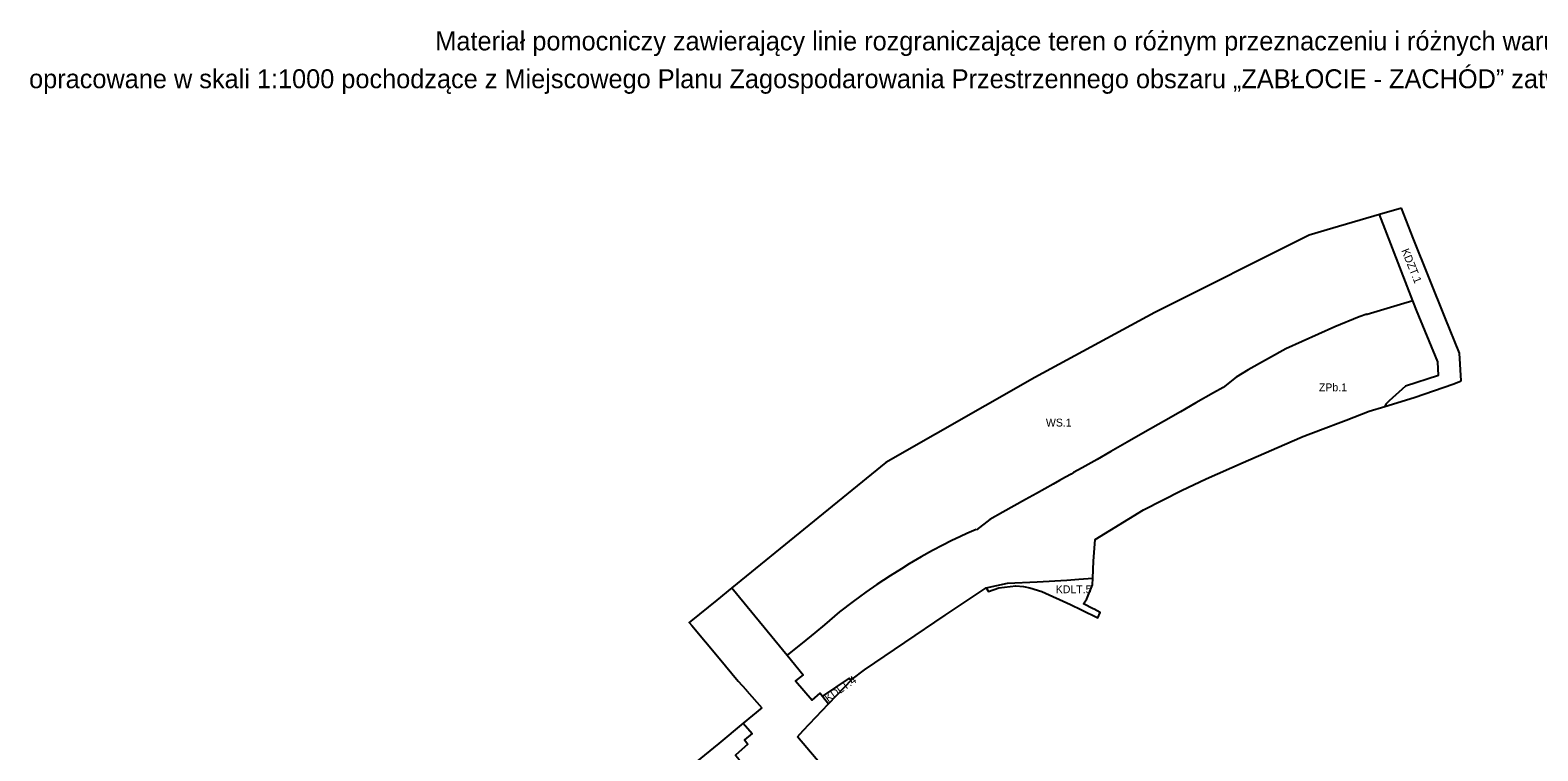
# Model space of a CAD drawing. Extents: x 7424719 to 7426158, y 5545504 to 5546892.
# Drawn here: x 7424719 to 7425675, y 5546434 to 5546892 of the extents above; entities that cross this region are included whole.
import ezdxf

# ---------------------------------------------------------------- set-up
doc = ezdxf.new("R2010")
doc.units = 0
for name, color, linetype in [('info', 7, 'Continuous'), ('Linie Rozgraniczajace', 7, 'Continuous'), ('Oznaczenia Przeznaczenia', 7, 'Continuous')]:
    doc.layers.add(name, color=color, linetype=linetype)

msp = doc.modelspace()

# ---------------------------------------------------------------- linework, layer by layer
at = {"layer": 'Linie Rozgraniczajace'}
for p, q in [((7425612.27, 5546672.62), (7425591.45, 5546665.84)), ((7425622.13, 5546667.19), (7425626.66, 5546669.16)), ((7425319.19, 5546574.73), (7425319.06, 5546574.76)), ((7425225.5, 5546464.3), (7425240.33, 5546479.92)), ((7425183.03, 5546461.75), (7425171.34, 5546452.02)), ((7425978.47, 5545533.55), (7425205.67, 5546443.4))]:
    msp.add_line(p, q, dxfattribs=at)
for points in [[(7425588.74, 5546778.78), (7425574.9, 5546774.69), (7425545.27, 5546765.93), (7425530.29, 5546761.5), (7425432.35, 5546712.59), (7425356.22, 5546671.39), (7425261.83, 5546617.35), (7425164.18, 5546537.93)], [(7425626.66, 5546669.16), (7425625.53, 5546686.75), (7425616.48, 5546709.23), (7425596.28, 5546759.6), (7425588.74, 5546778.78)], [(7425596, 5546719.98), (7425574.9, 5546774.69)], [(7425596, 5546719.98), (7425588.21, 5546717.58), (7425577.55, 5546714.42), (7425567.03, 5546711.27), (7425566.91, 5546711.21), (7425566.8, 5546711.49), (7425562.08, 5546709.78)], [(7425598.32, 5546713.96), (7425596.42, 5546718.89), (7425596, 5546719.98)], [(7425612.27, 5546672.62), (7425611.91, 5546681.27), (7425598.32, 5546713.96)], [(7425562.08, 5546709.78), (7425546.51, 5546703.41), (7425515.38, 5546689.56), (7425491.52, 5546676.23), (7425484.08, 5546671.46), (7425475.73, 5546664.94)], [(7425240.33, 5546479.92), (7425248.2, 5546485.91), (7425299.44, 5546520.42), (7425325.47, 5546537.95), (7425326.8, 5546535.6), (7425333.54, 5546537.81), (7425344.16, 5546539.19), (7425349.07, 5546538.68), (7425353.11, 5546537.94), (7425360.74, 5546535.49), (7425378.82, 5546527.36), (7425385.88, 5546523.93), (7425396.33, 5546518.85), (7425397.79, 5546522.18), (7425393.87, 5546524.25), (7425393.35, 5546524.53), (7425387.14, 5546527.81), (7425389.27, 5546530.8), (7425392.94, 5546539.7), (7425393.1, 5546543.95), (7425393.49, 5546554.7), (7425394.61, 5546568.62), (7425425.14, 5546587.32), (7425449.4, 5546599.68), (7425464.85, 5546607.08), (7425488.35, 5546617.45), (7425524.3, 5546633.04), (7425524.96, 5546633.32), (7425525.28, 5546633.46), (7425539.24, 5546638.77), (7425550.26, 5546642.95), (7425553.71, 5546644.26), (7425568.4, 5546649.83), (7425578.36, 5546652.87), (7425596.88, 5546658.51), (7425622.13, 5546667.19)], [(7425475.73, 5546664.94), (7425469.59, 5546661.55), (7425458.5, 5546655.19), (7425448.65, 5546649.59), (7425437.88, 5546643.41), (7425426.25, 5546636.78), (7425414.9, 5546630.28), (7425404.55, 5546624.26), (7425395.72, 5546619.27), (7425386.29, 5546613.97), (7425380.9, 5546610.95)], [(7425591.45, 5546665.84), (7425581.06, 5546656.51), (7425578.98, 5546654.46), (7425578.36, 5546652.87)], [(7425380.9, 5546610.95), (7425379.23, 5546610.02), (7425375.7, 5546608.05), (7425371.82, 5546605.87), (7425367.97, 5546603.71), (7425362.61, 5546600.71), (7425357.41, 5546597.76), (7425350.36, 5546593.87), (7425343.16, 5546589.86), (7425335.89, 5546585.77), (7425327.73, 5546581.26), (7425319.19, 5546574.73)], [(7425319.06, 5546574.76), (7425313.17, 5546572.28), (7425309.08, 5546570.38), (7425303.21, 5546567.57), (7425297.84, 5546564.88), (7425291.42, 5546561.47), (7425284.21, 5546557.48), (7425276.63, 5546553.02), (7425271.61, 5546549.95), (7425264.47, 5546545.46), (7425256, 5546539.89), (7425249.15, 5546535.14), (7425241.09, 5546529.28), (7425232.46, 5546522.56), (7425222.98, 5546514.3), (7425216.74, 5546509.25), (7425208.7, 5546502.82), (7425199.41, 5546495.33), (7425199.14, 5546495.11)], [(7425325.47, 5546537.95), (7425332.25, 5546539.38), (7425339.04, 5546540.81), (7425357.8, 5546541.75), (7425376.57, 5546542.7), (7425384.23, 5546543.28), (7425393.1, 5546543.95)], [(7425164.18, 5546537.93), (7425154.53, 5546530.08), (7425138.13, 5546516.73), (7425137.02, 5546515.83), (7425138.65, 5546513.89), (7425156.03, 5546493.2), (7425168.21, 5546478.7), (7425173.1, 5546473.1)], [(7425164.18, 5546537.93), (7425199.14, 5546495.11), (7425209.33, 5546482.62), (7425204.57, 5546478.95), (7425215.12, 5546466.5), (7425220.04, 5546471.01), (7425221.64, 5546469.05), (7425225.5, 5546464.3)], [(7425173.1, 5546473.1), (7425173.22, 5546472.96), (7425173.64, 5546472.49), (7425183.03, 5546461.75)], [(7425240.33, 5546479.92), (7425239.26, 5546479.69), (7425238.9, 5546480.15), (7425238.54, 5546480.61), (7425221.64, 5546469.05)], [(7425205.67, 5546443.4), (7425209.39, 5546447.33), (7425225.5, 5546464.3)], [(7425171.34, 5546452.02), (7425155.91, 5546439.18), (7425100.05, 5546393.63), (7425082.63, 5546379.87), (7425067.33, 5546367.48), (7425050.39, 5546353.84), (7425040.18, 5546345.6)], [(7425171.34, 5546452.02), (7425176.92, 5546445.38), (7425172.18, 5546441.45), (7425174.26, 5546438.77), (7425166.51, 5546431.64), (7425167.85, 5546429.93), (7425171.13, 5546425.76), (7425169.76, 5546423.76), (7425176.08, 5546414.76), (7425190.41, 5546394.33), (7425204.26, 5546383.55)]]:
    msp.add_lwpolyline(points, dxfattribs=at)

# ---------------------------------------------------------------- texts
at = {"layer": 'info'}
for s, p in [('Materiał pomocniczy zawierający linie rozgraniczające teren o różnym przeznaczeniu i różnych warunkach zagospodarowania terenu, ', (7424976.04, 5546878.81)), ('opracowane w skali 1:1000 pochodzące z Miejscowego Planu Zagospodarowania Przestrzennego obszaru „ZABŁOCIE - ZACHÓD” zatwierdzonego uchwałą RMK Nr LV/1528/21 z dnia 7 kwietnia 2021 r.', (7424718.39, 5546854.81))]:
    msp.add_text(s, height=12, dxfattribs=at).set_placement(p)
at = {"layer": 'Oznaczenia Przeznaczenia'}
for s, rotation, p in [('KDZT.1', 291.91043, (7425588.66, 5546751.89)), ('KDLT.4', 35.64638, (7425225.24, 5546465.12))]:
    msp.add_text(s, height=5, rotation=rotation, dxfattribs=at).set_placement(p)
for s, p in [('ZPb.1', (7425536.46, 5546662.54)), ('WS.1', (7425363.29, 5546640.19)), ('KDLT.5', (7425369.55, 5546534.44))]:
    msp.add_text(s, height=5, dxfattribs=at).set_placement(p)

doc.saveas('drawing.dxf')
